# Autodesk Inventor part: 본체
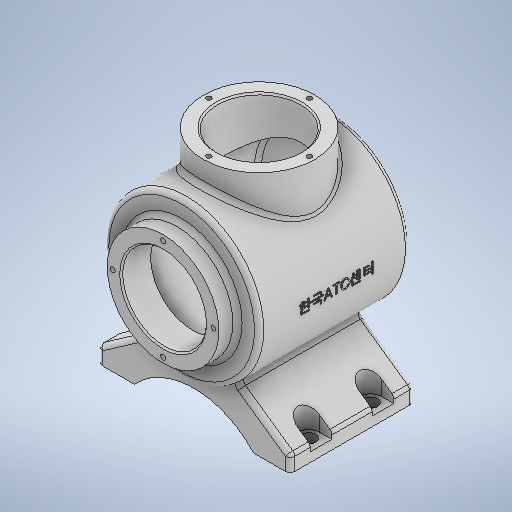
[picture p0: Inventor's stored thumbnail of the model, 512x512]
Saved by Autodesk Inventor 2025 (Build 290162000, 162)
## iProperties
Created: 2024-07
Part Number: 본체
Material: 일반
Document SubType Name: Modeling
Designer: 학생
Density: 2.7 g/cm^3
Appearance: 기본값
Mass: 1297.2 g
Surface Area: 1062.25 cm^2
Volume: 480.445 cm^3
Author: 학생
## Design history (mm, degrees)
sketch "스케치1"
  geometry: C1 r 50 at (0, 0); C2 r 36 at (0, 0); 1 further point
  constraints: 2 centre point, 2 coincident
  dimensions: "d0" = 100 diameter of C1; "d3" = 72 diameter of C2
extrude "돌출1" new body sketch "스케치1" distance "d1" = 108; taper "d2" = 0 deg
fillet "모깎기1" dims "d6" = 3
sketch "스케치2"
  geometry: L1 (-50, -108)-(50, -108) reference; L2 (143.33, 5)-(-131.324, 5); L3 (-47, 0)-(47, 0) reference; L4 (113, 5)-(-113, 5); A1 r 113 centre (0, 5) between (-113, 5) and (113, 5); 2 further points
  constraints: 4 end point, 3 point on circle, 3 point on line, 1 centre point, 1 collinear, 1 midpoint, 1 parallel
  dimensions: "d8" = 113 radius of A1
revolve "회전1" sketch "스케치2" stored, may be unused: angle "d9" = 90 deg
node "작업 평면1"
feature "쉘1" dims "d33" = 7
extrude "돌출5" join sketch "스케치1" distance "d34" = 12; taper "d35" = 0 deg
sketch "스케치3"
  geometry: L1 (0, -237.107)-(0, 83.685); L2 (36, 12)-(-36, 12) reference; C1 r 36 at (0, -50); 1 further point
  constraints: 2 end point, 2 point on line, 1 centre point, 1 vertical
  dimensions: "d11" = 72 diameter of C1; "d37" = 62 distance from line of C1.centre L2
extrude "돌출3" join sketch "스케치3" stored distance "d14" = 50; taper "d15" = 0 deg
fillet "모깎기2" dims "d16" = 3
fillet "모깎기6" dims "d28" = 3
node "작업 평면3"
sketch "스케치5"
  geometry: L1 (0, 68.499)-(0, -75.315); L2 (25.065, -41.138)-(62, -67); L3 (62, -67)-(62, -77); L4 (62, -77)-(38.5, -77); L5 (-24.439, -40.7)-(-62, -67); L6 (-62, -67)-(-62, -77); L7 (-62, -77)-(-38.5, -77); C1 r 43 at (0, 0) reference; A1 r 52.096 centre (0, -112.096) between (38.5, -77) and (-38.5, -77); A2 r 72.039 centre (0.911, 26.732) between (-24.439, -40.7) and (25.065, -41.138); 2 further points
  constraints: 14 end point, 5 point on circle, 2 centre point, 2 perpendicular, 2 point on line, 2 vertical, 3 other
  dimensions: "d39" = 17 distance from line of L4 point (0, -60); "d40" = 77 distance from line of L4 point (0, 0); "d41" = 10 distance of L2.end L3.end; "d42" = 55 deg angle of L3 L2; "d43" = 77 distance of L4.end L7.end; "d123" = 124 distance between parallel lines of L3 L6
extrude "돌출6" join sketch "스케치5" distance "d44" = 80; taper "d45" = 0 deg
sketch "스케치6"
  geometry: L1 (-38.5, 42.294)-(-38.5, -123.644); L2 (-124.492, -40)-(51.678, -40); L3 (23.5, 0)-(23.5, -80) reference; L4 (-100.5, 0)-(-100.5, -80) reference; L5 (0, 0)-(23.5, 0) reference; 7 further points
  constraints: 4 end point, 3 midpoint, 2 point on line, 2 symmetric about line, 1 horizontal, 1 vertical
  dimensions: "d53" = 108 distance of point (15.5, -20) point (-92.5, -20); "d54" = 108 distance of point (15.5, -60) point (-92.5, -60); "d55" = 40 distance of point (15.5, -60) point (15.5, -20); "d56" = 20 distance from line of point (15.5, -20) L5
hole "구멍1" sketch "스케치6" at (15.5, -20), (15.5, -60), (-92.5, -20), (-92.5, -60) diameter "d46" = 9; stored, may be unused: countersink angle "d50" = 90 deg, drill point angle "d52" = 0 deg; dims "d47" = 24, "d48" = 4, "d49" = 2, "d51" = 6
sketch "스케치7"
  geometry: C1 r 4.5 at (0, 0) reference; C2 r 4.5 at (0, -40) reference; 3 further points
  constraints: 2 coincident
hole "구멍2" sketch "스케치7" at (0, 0), (0, -40) diameter "d57" = 14; stored, may be unused: countersink angle "d61" = 90 deg, drill point angle "d63" = 0 deg; dims "d58" = 6, "d59" = 4, "d60" = 2, "d62" = 6
sketch "스케치8"
  geometry: C1 r 4.5 at (0, 0) reference; C2 r 4.5 at (0, -40) reference; 3 further points
  constraints: 2 coincident
hole "구멍3" sketch "스케치8" at (0, 0), (0, -40) diameter "d64" = 14; stored, may be unused: countersink angle "d68" = 90 deg, drill point angle "d70" = 0 deg; dims "d65" = 6, "d66" = 4, "d67" = 2, "d69" = 8
sketch "스케치9"
  geometry: L1 (-15.5, -20)-(8, -20) reference; L2 (-15.5, -20)-(-15.5, 60) reference; L3 (8, 60)-(-15.5, 60) reference; L4 (8, -20)-(8, 60) reference; L5 (-116, -20)-(-92.5, -20) reference; L6 (-116, -20)-(-116, 60) reference; L7 (-92.5, 60)-(-116, 60) reference; L8 (-92.5, -20)-(-92.5, 60) reference; L9 (28.226, -7)-(0, -7); L10 (0, -7)-(0, 7); L11 (0, 7)-(28.226, 7); L12 (28.226, 7)-(28.226, -7); L13 (31.115, 33)-(0, 33); L14 (0, 33)-(0, 47); L15 (0, 47)-(31.115, 47); L16 (31.115, 47)-(31.115, 33); L17 (-108, -7)-(-135.114, -7); L18 (-135.114, -7)-(-135.114, 7); L19 (-135.114, 7)-(-108, 7); L20 (-108, 7)-(-108, -7); L21 (-108, 33)-(-139.115, 33); L22 (-139.115, 33)-(-139.115, 47); L23 (-139.115, 47)-(-108, 47); L24 (-108, 47)-(-108, 33); C1 r 4.5 at (0, 40) reference; C2 r 4.5 at (0, 0) reference; C3 r 4.5 at (-108, 40) reference; C4 r 4.5 at (-108, 0) reference; 5 further points
  constraints: 32 end point, 8 parallel, 4 coincident, 4 horizontal, 4 midpoint, 4 perpendicular
  dimensions: "d73" = 14 distance between parallel lines of L11 L9; "d74" = 14 distance between parallel lines of L15 L13; "d75" = 14 distance between parallel lines of L19 L17; "d76" = 14 distance between parallel lines of L23 L21
extrude "돌출8" cut sketch "스케치9" distance "d77" = 20; taper "d78" = 0 deg
fillet "모깎기7" dims "d79" = 3
fillet "모깎기8" dims "d80" = 3
sketch "스케치10"
  geometry: C1 r 36 at (0, 0) reference; 2 further points
  constraints: 1 coincident
hole "구멍4" sketch "스케치10" at (0, 0) diameter "d81" = 54; stored, may be unused: countersink angle "d85" = 90 deg, drill point angle "d87" = 0 deg; dims "d82" = 6, "d83" = 4, "d84" = 2, "d86" = 19
chamfer "모따기1" distance "d88" = 1; stored, may be unused: second distance "d89" = 2, angle "d90" = 45 deg
sketch "스케치11"
  geometry: C1 r 36 at (0, 0) reference; 2 further points
  constraints: 1 coincident
hole "구멍5" sketch "스케치11" at (0, 0) diameter "d91" = 54; stored, may be unused: countersink angle "d95" = 90 deg, drill point angle "d97" = 0 deg; dims "d92" = 6, "d93" = 4, "d94" = 2, "d96" = 19
chamfer "모따기2" distance "d98" = 1; stored, may be unused: second distance "d99" = 2, angle "d100" = 45 deg
fillet "모깎기9" dims "d101" = 3
sketch "스케치12"
  geometry: L1 (0, 72.304)-(0, -92.289); L2 (-67.003, 0)-(67.003, 0); C1 r 36 at (0, 0) reference; 5 further points
  constraints: 5 point on line, 4 end point, 2 symmetric about line, 1 horizontal, 1 midpoint, 1 vertical
  dimensions: "d109" = 65 distance of point (0, -32.5) point (0, 32.5); "d110" = 65 distance of point (32.5, 0) point (-32.5, 0)
hole "구멍6" sketch "스케치12" at (0, 32.5), (-32.5, 0), (32.5, 0), (0, -32.5) diameter "d102" = 3.242; stored, may be unused: countersink angle "d106" = 90 deg, drill point angle "d108" = 118 deg; dims "d103" = 8, "d104" = 4, "d105" = 2, "d107" = 10
sketch "스케치13"
  geometry: L1 (0, 65.993)-(0, -106.174); L2 (-73.382, 0)-(92.175, 0); C1 r 36 at (0, 0) reference; 5 further points
  constraints: 6 point on line, 4 end point, 2 symmetric about line, 1 horizontal, 1 vertical
  dimensions: "d118" = 65 distance of point (0, -32.5) point (0, 32.5); "d119" = 65 distance of point (32.5, 0) point (-32.5, 0)
hole "구멍7" sketch "스케치13" at (0, 32.5), (-32.5, 0), (0, -32.5), (32.5, 0) diameter "d111" = 3.242; stored, may be unused: countersink angle "d115" = 90 deg, drill point angle "d117" = 118 deg; dims "d112" = 8, "d113" = 4, "d114" = 2, "d116" = 10
sketch "스케치14"
  geometry: L1 (-86.337, 71)-(75.152, 71); L2 (-73, 107)-(-73, 35) reference; 2 further points
  constraints: 2 end point, 2 point on line, 1 horizontal, 1 other
  dimensions: "d120" = 62 distance from line of point (-11, 71) L2
feature "엠보싱1" sketch "스케치14" dims "d121" = 0.5, "d122" = 0
node "솔리드1"
node "투영된 루프1"
node "투영된 루프2"
feature "A9D066F2-1C7D-4E18-AEED-F7BC21143FA4" dims "d46" = 9, "d47" = 24, "d48" = 4, "d49" = 2, "d50" = 90 deg, "d51" = 6, "d52" = 0
other parameters: "d10" = 65, "d29" = 0.5, "d30" = 2, "d31" = 0
